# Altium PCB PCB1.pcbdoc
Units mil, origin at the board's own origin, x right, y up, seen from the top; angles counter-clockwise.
Board outline 4595.5 x 2040.6 mil, 2 copper layers (Top Layer, Bottom Layer), stack 62.2 mil thick; 83 components, 64 nets, 301 pads, 109 vias.
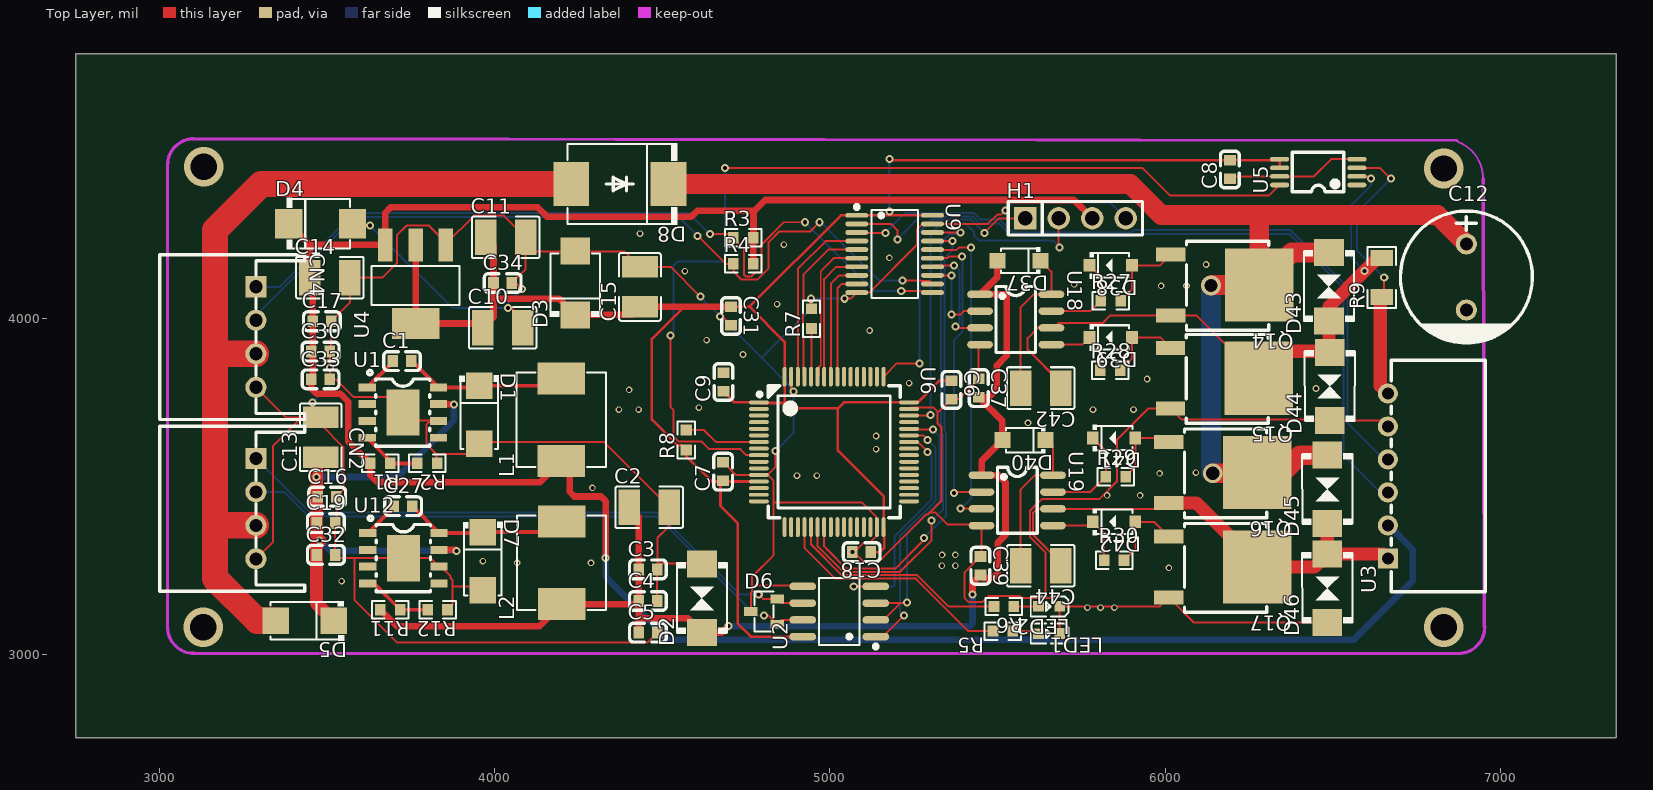
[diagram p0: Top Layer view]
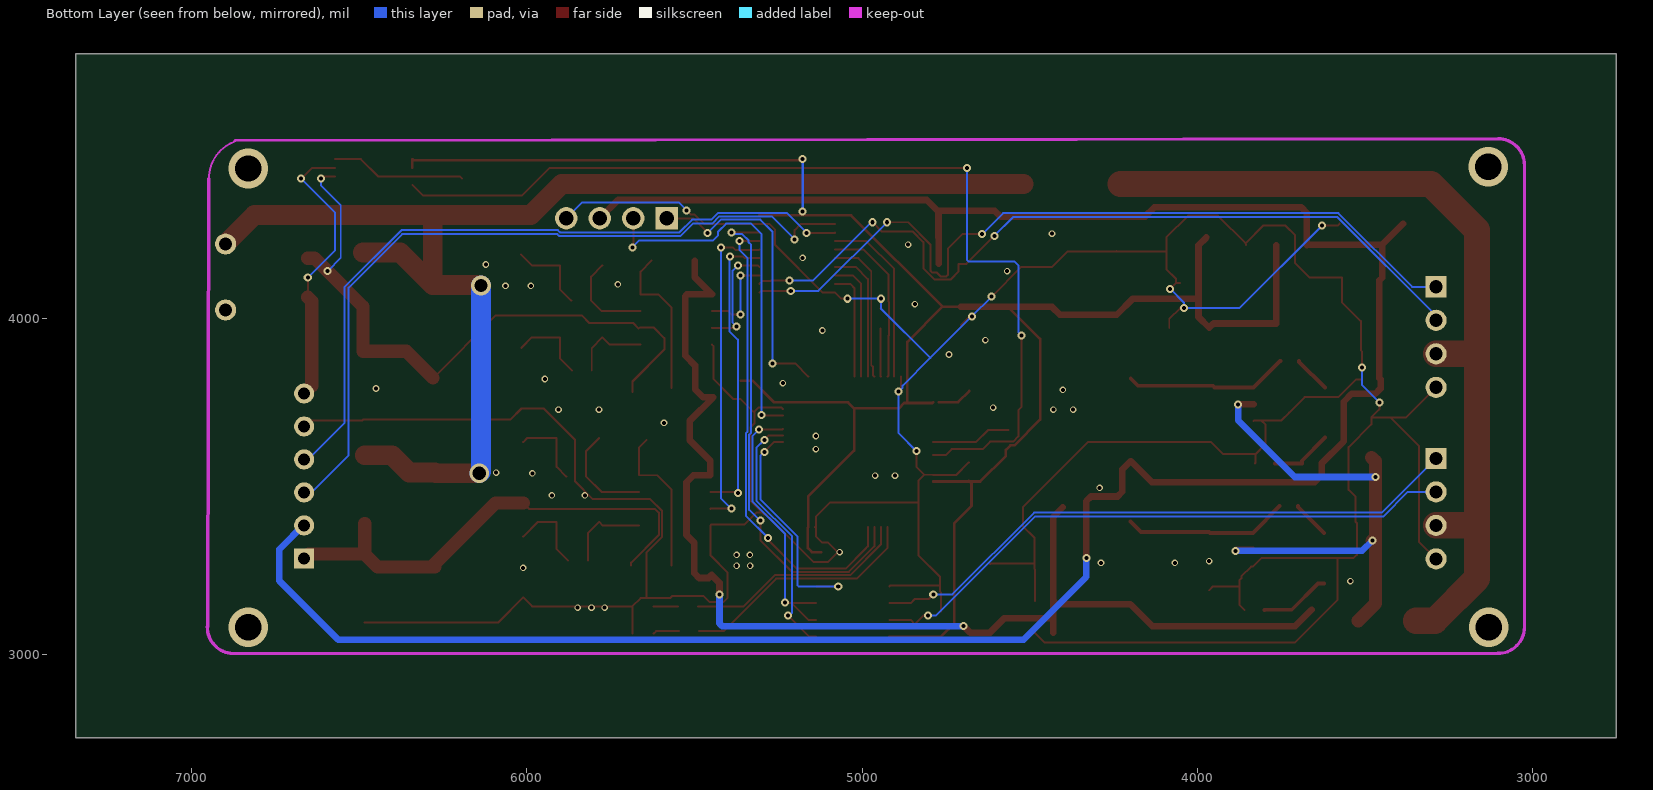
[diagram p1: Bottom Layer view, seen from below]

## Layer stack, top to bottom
Top Solder Mask Layer: solder mask 0.4, Dk 3.3
Top Layer: signal copper 1.4
Dielectric1: surface 59.4, FR4, Dk 4.5
Bottom Layer: signal copper 1.4
Bottom Solder Mask Layer: solder mask 0.4, Dk 3.3

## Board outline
7345.5,2750 2750,2750 2750,4790.6 7345.5,4790.6

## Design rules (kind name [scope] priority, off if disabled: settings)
BoardOutlineClearance copperThickness1oz [All] p0: genericclearance=10 ignorepadtopadclearanceinfootprint=FALSE except(0: Arc-SplitContinuation Track-SplitContinuation SMDPad-SplitContinuation THPad-SplitContinuation Via-SplitContinuation Fill-SplitContinuation Poly-SplitContinuation Region-SplitContinuation Text-SplitContinuation)
BoardOutlineClearance copperThickness2oz [All] p0: genericclearance=10 ignorepadtopadclearanceinfootprint=FALSE except(0: Arc-SplitContinuation Track-SplitContinuation SMDPad-SplitContinuation THPad-SplitContinuation Via-SplitContinuation Fill-SplitContinuation Poly-SplitContinuation Region-SplitContinuation Text-SplitContinuation)
BoardOutlineClearance otherClearance [All] p0: genericclearance=10 ignorepadtopadclearanceinfootprint=FALSE except(0: Arc-SplitContinuation Track-SplitContinuation SMDPad-SplitContinuation THPad-SplitContinuation Via-SplitContinuation Fill-SplitContinuation Poly-SplitContinuation Region-SplitContinuation Text-SplitContinuation)
Clearance copperThickness1oz [All] p1: gap=7 ignorepadtopadclearanceinfootprint=FALSE
Clearance copperThickness2oz [All] p1: gap=7 ignorepadtopadclearanceinfootprint=FALSE
Clearance otherClearance [All] p1: gap=7 ignorepadtopadclearanceinfootprint=FALSE
DiffPairsRouting differentialPair [All] p1: maxuncoupledlength=10 minlimit=6 maxlimit=Infinity mostfreqgap=6 toplayer_minwidth=5 toplayer_prefwidth=10 toplayer_maxwidth=100 bottomlayer_minwidth=5 bottomlayer_prefwidth=10 bottomlayer_maxwidth=100
PasteMaskExpansion pasteMaskExpansion [All] p1: expansion=0
PlaneConnect innerPlane [All] p1: planeconnectstyle=Direct reliefexpansion=20 reliefentries=4 reliefconductorwidth=10 reliefairgap=10
PolygonConnect copperRegion [All] p1: connectstyle=Direct reliefentries=4 reliefconductorwidth=10 polygonreliefangle="90 Angle" airgapwidth=10
RoutingVias viaSize [All] p1: viastyle="Through Hole" holewidth=12.0078 minholewidth=11.811 maxholewidth=248.0314 width=12.0078 minwidth=11.811 maxwidth=248.0314
SolderMaskExpansion solderMaskExpansion [IsVia] p1: useseparateexpansions=TRUE expansion=-1000 expansionbottom=-1000
SolderMaskExpansion solderMaskExpansion [All] p2: useseparateexpansions=TRUE expansion=2 expansionbottom=2
Width copperThickness1oz [All] p1: maxlimit=100 minlimit=5 preferedwidth=6
Width copperThickness2oz [All] p1: maxlimit=100 minlimit=8 preferedwidth=10
Width l24V [All] p1: maxlimit=100 minlimit=4 preferedwidth=39
Width i5V [All] p1: maxlimit=100 minlimit=5 preferedwidth=20
Width i3V [All] p1: maxlimit=100 minlimit=5 preferedwidth=8

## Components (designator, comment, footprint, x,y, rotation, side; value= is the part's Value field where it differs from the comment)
C1 "100nF" C0603#1 3723.3,3873.7 r0 top
C2 "10uF" C1210#1 4460.6,3437.7 r0 top
C3 "100nF" C0603#2 4456.7,3252.6 r0 top
C4 "100nF" C0603#2 4456.7,3158.1 r0 top
C5 "100nF" C0603#2 4456.7,3063.7 r0 top
C6 "100nF" C0603#1 5362.2,3788.1 r270 top
C7 "100nF" C0603#3 4681.1,3544 r90 top
C8 "100nF" C0603#3 6192.9,4445.6 r90 top
C9 "100nF" C0603#1 4682.3,3811.5 r90 top
C10 "10uF" C1210#1 4023.6,3973.1 r0 top
C11 "10uF" C1210#2 4032.2,4243 r0 top
C12 "470uF" CAP-TH_BD10.0-P5.00-D0.6-FD 6898.6,4124.7 r270 top
C13 "10uF" C1210#1 3480.3,3646.3 r90 top
C14 "10uF" C1210#3 3507.9,4122.7 r0 top
C15 "10uF" C1210#3 4433.1,4095.2 r90 top
C16 "100nF" C0603#2 3500,3469.2 r0 top
C17 "100nF" C0603#3 3484.3,3992.8 r0 top
C18 "100nF" C0603#1 5094.5,3303.8 r180 top
C19 "100nF" C0603#3 3496.1,3390.4 r0 top
C27 "100nF" C0603#3 3726.7,3440.9 r0 top
C30 "100nF" C0603#1 3480.3,3902.2 r0 top
C31 "100nF" C0603#3 4704.7,4008.5 r270 top
C32 "100nF" C0603#3 3496.1,3295.9 r0 top
C33 "100nF" C0603#1 3480.3,3819.6 r0 top
C34 "100nF" C0603#1 4023.6,4107 r0 top
C37 "100nF" C0603#2 5443.7,3793.3 r270 top
C39 "100nF" C0603#2 5448.7,3263.3 r270 top
C42 "10uF" C1210#3 5628.7,3793.3 r180 top
C44 "10uF" C1210#3 5628.7,3263.3 r180 top
CN2 "2.54-4P WZ-D" CONN-TH_2.54-4P-WZ-D 3287.4,3433.7 r270 top
CN4 "2.54-4P WZ-D" CONN-TH_2.54-4P-WZ-D 3287.4,3945.6 r270 top
D1 "B340A-E3/61T" SMA_L4.3-W2.6-LS5.2-RD 3953.3,3713.7 r270 top
D2 "SMBJ36CA" SMB_L4.6-W3.6-LS5.4-BI#1 4618.1,3166 r90 top
D3 "SMBJ5.0A" SMB_L4.6-W3.6-LS5.4-RD 4240.2,4107 r90 top
D4 "SMBJ5.0A" SMB_L4.6-W3.6-LS5.4-RD 3480.3,4284.1 r0 top
D5 "B340A-E3/61T" SMA_L4.3-W2.6-LS5.2-RD 3433.1,3099.1 r180 top
D6 "SM712" SOT-23-3_L2.9-W1.3-P1.90-LS2.4-BR 4803.1,3126.7 r0 top
D7 "B340A-E3/61T" SMA_L4.3-W2.6-LS5.2-RD 3964.4,3276.8 r270 top
D8 "B560C" SMC_L6.9-W5.9-LS7.9-RD 4373,4402.2 r180 top
D37 "FR107W" SOD-123FL_L2.7-W1.8-LS3.8-RD 5563.7,4173.3 r180 top
D38 "1N4148W" SOD-123_L2.7-W1.6-LS3.7-FD 5837.7,4159.4 r180 top
D39 "1N4148W" SOD-123_L2.7-W1.6-LS3.7-FD 5837.7,3944.4 r180 top
D40 "FR107W" SOD-123FL_L2.7-W1.8-LS3.8-RD 5578.7,3638.3 r180 top
D41 "1N4148W" SOD-123_L2.7-W1.6-LS3.7-FD 5847.7,3644.4 r180 top
D42 "1N4148W" SOD-123_L2.7-W1.6-LS3.7-FD 5847.7,3394.4 r180 top
D43 "SMBJ36CA" SMB_L4.6-W3.6-LS5.4-BI#2 6488.7,4096.1 r90 top
D44 "SMBJ36CA" SMB_L4.6-W3.6-LS5.4-BI#1 6490.7,3798.1 r90 top
D45 "SMBJ36CA" SMB_L4.6-W3.6-LS5.4-BI#2 6483.7,3491.1 r90 top
D46 "SMBJ36CA" SMB_L4.6-W3.6-LS5.4-BI#2 6483.7,3196.1 r90 top
H1 "PZ254V-11-04P" HDR-TH_4P-P2.54-V-M 5732.3,4299.9 r0 top
L1 "22uH" IND-SMD_L7.0-W6.6_FXL0630 4198.3,3698.7 r90 top
L2 "22uH" IND-SMD_L7.0-W6.6_FXL0630 4199.4,3271.8 r90 top
LED1 "" LED_0603 5651.6,3060.7 r180 top
LED2 "" LED_0603 5651.6,3141.8 r180 top
Q14 "CMD100N08A" TO-252-3_L6.5-W5.8-P4.58-LS9.5-BR#1 6148.7,4101.1 r180 top
Q15 "CMD100N08A" TO-252-3_L6.5-W5.8-P4.58-LS9.5-BR#1 6147.7,3823 r180 top
Q16 "CMD100N08A" TO-252-3_L6.5-W5.8-P4.58-LS9.5-BR#2 6142.7,3541.3 r180 top
Q17 "CMD100N08A" TO-252-3_L6.5-W5.8-P4.58-LS9.5-BR#1 6142.7,3259.5 r180 top
R1 "10K" R0603#1 3658.3,3568.7 r180 top
R2 "10K" R0603#1 3798.3,3568.7 r180 top
R3 "10K" R0603#1 4741.2,4241.8 r0 top
R4 "10K" R0603#1 4741.2,4164.1 r0 top
R5 "10K" R0603#2 5516,3068.5 r180 top
R6 "10K" R0603#1 5518.7,3141.8 r180 top
R7 "10kΩ" R0603#1 4944.9,4000.7 r90 top
R8 "10kΩ" R0603#1 4570.9,3638.5 r90 top
R9 "10mΩ" R1206 6645.7,4122.7 r90 top
R11 "10K" R0603#2 3688.4,3132.1 r180 top
R12 "10K" R0603#3 3829.4,3131.8 r180 top
R27 "10K" R0603#1 5837.7,4054.4 r0 top
R28 "10K" R0603#2 5835.9,3846.3 r0 top
R29 "10K" R0603#1 5852.7,3529.4 r0 top
R30 "10K" R0603#1 5847.7,3279.4 r0 top
U1 "TPS5430DDAR" ESOP-8_L4.9-W3.9-P1.27-LS6.0-TL-EP 3725.6,3720.3 r0 top
U2 "SP3485EEN(UMW)" SOP-8_L5.0-W4.0-P1.27-LS6.0-BL 5027.6,3126.7 r90 top
U3 "WAFER-XH254WZ-6A" CONN-TH_6P-P2.50_WAFER-XH254WZ-6A 6664.4,3531.2 r90 top
U4 "AMS1117-3.3" SOT-223-3_L6.5-W3.4-P2.30-LS7.0-BR 3763.8,4103 r90 top
U5 "INA240A1PWR" TSSOP-8_L4.4-W3.0-P0.65-LS6.4-BL 6456.7,4437.7 r90 top
U6 "STM32F103RCT6" LQFP-64_L10.0-W10.0-P0.50-LS12.0-BL 5011.8,3603 r270 top
U9 "74HC245PW,118" TSSOP-20_L6.5-W4.4-P0.65-LS6.4-BL 5192.9,4193.6 r270 top
U12 "TPS5430DDAR" ESOP-8_L4.9-W3.9-P1.27-LS6.0-TL-EP 3727.5,3285.8 r0 top
U18 "EG2104S" SOIC-8_L5.0-W4.0-P1.27-LS6.0-BL 5554.1,3997.9 r270 top
U19 "EG2104S" SOIC-8_L5.0-W4.0-P1.27-LS6.0-BL 5558.7,3458.3 r270 top

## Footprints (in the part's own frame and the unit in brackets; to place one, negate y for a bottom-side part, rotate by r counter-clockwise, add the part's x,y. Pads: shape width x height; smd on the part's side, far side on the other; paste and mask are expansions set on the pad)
C0603#1 [mil]
  rect 31.5x35.4 smd: 1(-27.5,0) 2(27.6,0)
  silkscreen extent -55,-28 55,28
C0603#2 [mil]
  rect 31.5x35.4 smd: 1(-27.6,0) 2(27.6,0)
  silkscreen extent -55,-28 55,28
C0603#3 [mil]
  rect 31.5x35.4 smd: 1(-27.6,0) 2(27.5,0)
  silkscreen extent -55,-28 55,28
C1210#1 [mil]
  rect 64.4x106.3 smd paste-3937 mask+2: 1(-59.7,0) 2(59.8,0)
  silkscreen extent -101,-62 101,62
C1210#2 [mil]
  rect 64.4x106.3 smd paste-3937 mask+2: 1(-59.7,0) 2(59.7,0)
  silkscreen extent -101,-62 101,62
C1210#3 [mil]
  rect 64.4x106.3 smd paste-3937 mask+2: 1(-59.8,0) 2(59.7,0)
  silkscreen extent -101,-62 101,62
CAP-TH_BD10.0-P5.00-D0.6-FD [mil]
  round 63 hole 39.4 paste+0 mask+2: 1(-98.4,0) 2(98.4,0)
  silkscreen extent -197,-197 200,197
CONN-TH_2.54-4P-WZ-D [mil]
  rect 63x63 hole 39.4 paste+0 mask+2: 1(-150,0)
  round 63 hole 39.4 paste+0 mask+2: 2(-50,0) 3(50,0) 4(150,0)
  silkscreen extent -246,-287 246,146
CONN-TH_6P-P2.50_WAFER-XH254WZ-6A [mil]
  rect 60x60 hole 36: 1(-246.1,0)
  round 60 hole 36: 2(-147.7,0) 3(-49.2,0) 4(49.2,0) 5(147.6,0) 6(246,0)
  silkscreen extent -345,-290 345,-10
ESOP-8_L4.9-W3.9-P1.27-LS6.0-TL-EP [mm]
  rect 1.3x0.599 smd: 1(-2.7,1.905) 2(-2.7,0.635) 3(-2.7,-0.635) 4(-2.7,-1.905) 5(2.7,-1.905) 6(2.7,-0.635) 7(2.7,0.635) 8(2.7,1.905)
  rect 2.499x3.5 smd: 9(0,0)
  silkscreen extent -2.67,-2.55 2.05,3.2
HDR-TH_4P-P2.54-V-M [mil]
  rect 66.9x66.9 hole 43.3: 1(-150,0)
  round 66.9 hole 43.3: 2(-50,0) 3(50,0) 4(150,0)
  silkscreen extent -200,-50 200,50
IND-SMD_L7.0-W6.6_FXL0630 [mil]
  rect 95.4x142.5 smd: 1(123.1,0) 2(-123.2,0)
  silkscreen extent -141,-133 141,133
LED_0603 [mil]
  rect 31.5x31.5 smd paste+0 mask+2: 1(-33.5,-0.4) 2(29.5,-0.2)
  silkscreen extent -61,-30 53,30
LQFP-64_L10.0-W10.0-P0.50-LS12.0-BL [mil]
  oval 11.8x59.1 smd: 1(-147.7,-223.9) 2(-128,-223.9) 3(-108.3,-223.9) 4(-88.6,-223.9) 5(-68.9,-223.9) 6(-49.2,-223.9) 7(-29.6,-223.9) 8(-9.9,-223.9) 9(9.8,-223.9) 10(29.5,-223.9) 11(49.2,-223.9) 12(68.9,-223.9) 13(88.5,-223.9) 14(108.2,-223.9) 15(127.9,-223.9) 16(147.6,-223.9) 33(147.6,224) 34(127.9,224) 35(108.2,224) 36(88.5,224) 37(68.9,224) 38(49.2,224) 39(29.5,224) 40(9.8,224) 41(-9.9,224) 42(-29.6,224) 43(-49.2,224) 44(-68.9,224) 45(-88.6,224) 46(-108.3,224) 47(-128,224) 48(-147.7,224)
  oval 59.1x11.8 smd: 17(224.4,-147.2) 18(224.4,-127.5) 19(224.4,-107.8) 20(224.4,-88.1) 21(224.4,-68.4) 22(224.4,-48.7) 23(224.4,-29.1) 24(224.4,-9.4) 25(224.4,10.3) 26(224.4,30) 27(224.4,49.7) 28(224.4,69.4) 29(224.4,89.1) 30(224.4,108.7) 31(224.4,128.4) 32(224.4,148.1) 49(-224.4,148.1) 50(-224.4,128.4) 51(-224.4,108.7) 52(-224.4,89.1) 53(-224.4,69.4) 54(-224.4,49.7) 55(-224.4,30) 56(-224.4,10.3) 57(-224.4,-9.4) 58(-224.4,-29.1) 59(-224.4,-48.7) 60(-224.4,-68.4) 61(-224.4,-88.1) 62(-224.4,-107.8) 63(-224.4,-127.5) 64(-224.4,-147.2)
  silkscreen extent -197,-228 197,197
R0603#1 [mil]
  rect 31.8x34 smd paste-3937 mask+2: 1(-29.7,0) 2(29.6,0)
  silkscreen extent -55,-26 54,26
R0603#2 [mil]
  rect 31.8x34 smd paste-3937 mask+2: 1(-29.6,0) 2(29.7,0)
  silkscreen extent -54,-26 55,26
R0603#3 [mil]
  rect 31.8x34 smd paste-3937 mask+2: 1(-29.7,0) 2(29.7,0)
  silkscreen extent -54,-26 54,26
R1206 [mil]
  rect 47.5x67 smd paste-3937 mask+2: 1(-58.2,0) 2(58.2,0)
  silkscreen extent -91,-43 91,43
SMA_L4.3-W2.6-LS5.2-RD [mil]
  rect 78.7x78.7 smd: 1(-86.6,0) 2(86.6,0)
  silkscreen extent -117,-59 102,59
SMB_L4.6-W3.6-LS5.4-BI#1 [mil]
  rect 80.6x88.2 smd: 1(-102,0) 2(102,0)
  silkscreen extent -105,-75 108,75
SMB_L4.6-W3.6-LS5.4-BI#2 [mil]
  rect 80.6x88.2 smd: 1(-102.1,0) 2(102,0)
  silkscreen extent -105,-75 108,75
SMB_L4.6-W3.6-LS5.4-RD [mil]
  rect 80.6x88.2 smd: 1(-95,0) 2(95,0)
  silkscreen extent -100,-77 88,77
SMC_L6.9-W5.9-LS7.9-RD [mil]
  rect 106.3x129.9 smd: 1(-145.2,0) 2(145.1,0)
  silkscreen extent -172,-122 157,122
SOD-123_L2.7-W1.6-LS3.7-FD [mil]
  rect 34.6x37.8 smd: 1(-63.4,0) 2(63.4,0)
  silkscreen extent -54,-39 63,40
SOD-123FL_L2.7-W1.8-LS3.8-RD [mil]
  rect 47.2x47.2 smd: 1(-64.4,0) 2(64.3,0)
  silkscreen extent -63,-40 54,39
SOIC-8_L5.0-W4.0-P1.27-LS6.0-BL [mil]
  oval 22.4x76.8 smd: 1(-75,-106.5) 2(-25,-106.5) 3(25,-106.5) 4(75,-106.5) 5(75,106.5) 6(25,106.5) 7(-25,106.5) 8(-75,106.5)
  silkscreen extent -98,-59 98,59
SOP-8_L5.0-W4.0-P1.27-LS6.0-BL [mil]
  oval 22.6x80.1 smd: 1(-75,-108.9) 2(-25,-108.9) 3(25,-108.9) 4(75,-108.9) 5(75,109) 6(25,109) 7(-25,109) 8(-75,109)
  silkscreen extent -110,-115 99,60
SOT-23-3_L2.9-W1.3-P1.90-LS2.4-BR [mil]
  rect 39.4x25.6 smd: 1(39.4,-37.4) 2(39.4,37.4) 3(-39.3,0)
  silkscreen extent -28,-60 29,60
SOT-223-3_L6.5-W3.4-P2.30-LS7.0-BR [mil]
  rect 98.4x43.3 smd: 1(117,-90.5) 2(117,0) 3(117,90.6)
  rect 92.1x141.7 smd: 4(-116.9,0)
  silkscreen extent -62,-131 54,131
TO-252-3_L6.5-W5.8-P4.58-LS9.5-BR#1 [mil]
  rect 87.3x41.9 smd: 1(131.8,-90.5) 3(131.8,90.6)
  rect 204.9x218.6 smd: 2(-131.9,0)
  silkscreen extent -160,-130 85,135
TO-252-3_L6.5-W5.8-P4.58-LS9.5-BR#2 [mil]
  rect 87.3x41.9 smd: 1(131.8,-90.6) 3(131.8,90.5)
  rect 204.9x218.6 smd: 2(-131.9,0)
  silkscreen extent -160,-130 85,135
TSSOP-8_L4.4-W3.0-P0.65-LS6.4-BL [mil]
  oval 13.9x57.2 smd: 1(-38.4,-115.2) 2(-12.8,-115.2) 3(12.8,-115.2) 4(38.4,-115.2) 5(38.4,115.2) 6(12.8,115.2) 7(-12.8,115.2) 8(-38.4,115.2)
  silkscreen extent -59,-76 59,77
TSSOP-20_L6.5-W4.4-P0.65-LS6.4-BL [mil]
  oval 14.3x68.6 smd: 1(-115.1,-113) 2(-89.6,-113) 3(-64,-113) 4(-38.4,-113) 5(-12.8,-113) 6(12.8,-113) 7(38.4,-113) 8(64,-113) 9(89.6,-113) 10(115.2,-113) 11(115.2,113) 12(89.6,113) 13(64,113) 14(38.4,113) 15(12.8,113) 16(-12.8,113) 17(-38.4,113) 18(-64,113) 19(-89.6,113) 20(-115.1,113)
  silkscreen extent -146,-119 131,70

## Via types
v1: diameter 24, hole 12, Top Layer to Bottom Layer, 59 vias
v2: diameter 19.7, hole 12, Top Layer to Bottom Layer, 44 vias
v3: diameter 118.1, hole 78.7, Top Layer to Bottom Layer, 4 vias
v4: diameter 59.1, hole 39.4, Top Layer to Bottom Layer, 2 vias

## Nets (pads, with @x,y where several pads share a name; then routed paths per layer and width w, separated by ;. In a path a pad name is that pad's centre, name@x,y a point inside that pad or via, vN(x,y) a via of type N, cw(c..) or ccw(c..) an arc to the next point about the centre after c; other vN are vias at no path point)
3.3V: C6.1 C7.1 C8.2 C9.1 C10.1 C11.1 C15.1 C18.1 C31.1 C34.1 D3.1 R8.1 U2.8 U4.2 U4.4 U5.5 U5.6 U6.1 U6.13 U6.32 U6.48 U6.64 U9.1 U9.20 | length 6564.1
  Top Layer w7.9: 4564,4035.4 4468.5,3939.9 4468.5,3699.1 4544.9,3622.7 4557,3622.7 R8.1 4570.9,3591.2 4647.6,3514.5 C7.1@4679.1,3514.5 ; C9.1@4679.8,3785.2 4713.7,3751.3 U6.1@4771.5,3751.3 ; C7.1 C7.1@4679.1,3514.5 ; C31.1 4759.8,4036.1 ; U6.13 C7.1@4679.1,3514.5 ; U6.1 4789.8,3748.7 4865.1,3748.7 ; U2.8 4764,3051.7 4724.4,3091.2 4724.4,3390.4 4673.2,3441.6 4673.2,3508.5 C7.1@4679.1,3514.5 ; C18.1 5149.6,3303.8 5161.4,3315.6 5161.4,3377.1 U6.32 5159.9,3470.7 5023.6,3607 5023.6,3733 ; v1(5177.2,4319.6) 5188,4308.7 ; v1(5177.2,4477) 5181.1,4473.1 C8.2 6338.5,4473.1 U5.5 U5.6 ; U9.20 5188,4308.7 ; C6.1 5326.8,3815.6 5261.8,3750.7 U6.48 5041.3,3750.7 5023.6,3733 ; 4759.8,4036.1 5032.5,4308.7 U9.1 5188,4308.7 ; 4759.8,4036.1 4864.6,3931.3 U6.64 4864.6,3749.2 4865.1,3748.7 ; 4865.1,3748.7 4874,3748.7 4889.8,3733 5023.6,3733
  Top Layer w19.7: U4.2 U4.4 3950.9,3986.1 C10.1 3996.1,4005.3 3996.1,4060.4 ; C11.1 3996.1,4219.4 C34.1 3996.1,4060.4 ; C31.1 4704,4035.4 4564,4035.4 C15.1 4409.6,4012 D3.1 4191.7,4060.4 3996.1,4060.4
  Bottom Layer w7.9: v1(5177.2,4319.6) v1(5177.2,4477)
12V: C2.1 C3.1 C4.1 C5.1 C37.2 C39.2 D2.1 D37.2 D40.2 L2.2 R11.2 U18.1 U19.1 | length 3658.1
  Top Layer w19.7: R11.2 3707.5,3083.3 4134.1,3083.3 L2.2 4419.6,3148.6 C4.1 ; C2.1 4429.1,3409.4 C3.1 C4.1 ; C5.1 4429.1,3115.6 ; v1(4696.8,3083.3) 4677.5,3064 D2.1 4575.1,3107 4437.8,3107 4429.1,3115.6 ; v1(5425.2,3177.8) 5425.2,3212.2 C39.2 5457.6,3226.9 5486.1,3226.9 5500,3240.8 5500,3331.4 5523.6,3355 5523.6,3512.5 5502.8,3533.3 U19.1 5452.2,3576.2 D40.2 5514.4,3695.1 C37.2 5473.7,3765.7 5498,3790 5498,3860.9 5527.6,3890.4 5527.6,4067.6 5522.2,4072.9 U18.1 5499.4,4124.7 D37.2 ; 4429.1,3115.6 C4.1
  Bottom Layer w19.7: v1(4696.8,3083.3) 5417.3,3083.3 5425.2,3091.2 v1(5425.2,3177.8)
24V: C13.1 C16.1 C19.1 C32.1 D5.1 U1.7 U12.7 | length 1565.6
  Top Layer w19.7: U1.7 3877.5,3745.3 v1(3878,3744.8) ; U12.7 3882.8,3310.8 v1(3885.8,3307.8)
  Top Layer w39.4: v1(3476.4,3339.3) v1@3478.5,3337.1 ; C13.1 3468.5,3574.8 v1(3468.5,3528.2) C19.1 C32.1 3468.5,3150.3 D5.1
  Bottom Layer w19.7: v1(3468.5,3528.2) 3708.7,3528.2 3878,3697.5 v1(3878,3744.8) ; v1(3476.4,3339.3) 3507.9,3307.8 v1(3885.8,3307.8)
24V-M: C12.1 D8.1 D43.2 D45.2 Q14.2 Q16.2 | length 3983.1
  Top Layer w59.1: D8.1 5895.7,4402.2 5988.2,4309.7 6282.2,4309.7 ; v4(6136.8,4099.1) 6138.8,4101.1 Q14.2 ; v4(6141.7,3539.1) 6272.3,3539.1 Q16.2 6350.7,3541.3 6402.5,3593.1 D45.2 ; D43.2 6377.6,4198.1 Q14.2 ; C12.1 6812,4309.7 6282.2,4309.7 ; Q14.2 6280.6,4308.1 6282.2,4309.7
  Bottom Layer w59.1: v4(6136.8,4099.1) 6136.8,3544 v4(6141.7,3539.1)
24V-P: CN2.3 CN4.3 D5.2 D8.2 | length 2637.3
  Top Layer w78.7: CN2.3 3287.2,3383.6 3165.1,3383.6 ; CN4.3 3165.1,3895.6 ; D5.2 3291.1,3099.1 3165.1,3225.1 3165.1,3383.6 ; D8.2 3303.1,4402.2 3165.1,4264.2 3165.1,3895.6 ; 3165.1,3383.6 3165.1,3895.6
$1N1: C1.1 U1.1 | length 110.1
  Top Layer w11.8: U1.1 3695.8,3871.7 C1.1
$1N2: C27.1 U12.1 | length 112.4
  Top Layer w11.8: U12.1 3699.1,3438.7 C27.1
$1N3: C1.2 D1.1 L1.1 U1.8 | length 490.9
  Top Layer w11.8: C1.2 3753.5,3873.7 U1.8 3948.3,3795.3 D1.1 4176.8,3800.3 L1.1
$1N4: C27.2 D7.1 L2.1 U12.8 | length 492.8
  Top Layer w11.8: C27.2 3833.8,3361.3 U12.8 3961.8,3360.8 D7.1 4167.9,3363.4 L2.1
$1N7: R1.1 R2.2 U1.4 | length 185.8
  Top Layer w11.8: U1.4 3688,3576.6 R1.1 R2.2
$1N8: R11.1 R12.2 U12.4 | length 211.3
  Top Layer w11.8: U12.4 3639.4,3210.8 R11.1 3799.4,3132.1 R12.2
$1N71: U6.57 U9.8 | length 365.1
  Top Layer w5.9: U6.57 5002.4,4104.6 5027.4,4129.6 U9.8
$1N72: U6.58 U9.7 | length 403.6
  Top Layer w5.9: U6.58 4982.7,4118.7 5019.3,4155.2 U9.7
$1N73: U6.59 U9.6 | length 442.1
  Top Layer w5.9: U6.59 4967.9,3832.3 4967.9,3857.2 4972.4,3861.7 4972.4,4142.1 5011.1,4180.8 U9.6
$1N74: U6.61 U9.5 | length 497.5
  Top Layer w5.9: U6.61 4921.3,3829.9 4921.3,3949.1 4918.9,3951.4 4918.9,4049.9 4921.3,4052.2 4921.3,4132.8 4994.8,4206.4 U9.5
$1N75: U6.62 U9.4 | length 532.1
  Top Layer w5.9: U6.62 4904,4149.3 4986.7,4232 U9.4
$1N90: C44.2 D40.1 U19.8 | length 455.5
  Top Layer w5.9: C44.2 5569,3490.9 5611.4,3533.3 U19.8 5665.2,3616.2 D40.1
$1N92: H1.1 U6.49 | length 881.3
  Top Layer w5.9: U6.49 5199.3,3866.8 v1(5267.7,3866.8) ; v1(5460.6,4256.6) 5503.9,4299.9 H1.1
  Bottom Layer w5.9: v1(5267.7,3866.8) 5267.7,4260.5 5303.1,4295.9 5421.3,4295.9 v1(5460.6,4256.6)
$1N93: H1.2 U6.46 | length 1126.3
  Top Layer w5.9: U6.46 5297.2,3711.3 v1(5299.2,3713.3) ; H1.2 5682.3,4216 v1(5685,4213.3)
  Bottom Layer w5.9: v1(5299.2,3713.3) 5299.2,4252.6 5330.7,4284.1 5405.5,4284.1 5429.1,4260.5 5429.1,4248.7 5444.9,4233 5665.4,4233 v1(5685,4213.3)
$1N120: D38.1 Q14.1 R27.2 | length 248.2
  Top Layer w5.9: R27.2 5901.1,4088.1 D38.1 5984.7,4159.4 Q14.1
$1N121: D41.1 Q16.1 R29.2 | length 231.9
  Top Layer w5.9: R29.2 5911.1,3558.1 D41.1 5998.4,3644.4 Q16.1
$1N122: D42.1 Q17.1 R30.2 | length 247.3
  Top Layer w5.9: R30.2 5911.1,3313.1 D42.1 5966.6,3394.4 Q17.1
$1N123: D39.1 Q15.1 R28.2 | length 240.4
  Top Layer w5.9: R28.2 5901.1,3881.8 D39.1 5985.1,3944.4 Q15.1
$1N124: D38.2 R27.1 U18.7 | length 279.4
  Top Layer w5.9: U18.7 5776.6,4022.9 R27.1 5808,4125.6 D38.2
$1N125: D39.2 R28.1 U18.5 | length 234
  Top Layer w5.9: U18.5 5752.8,3922.9 D39.2 5806.3,3912.4 R28.1
$1N126: D41.2 R29.1 U19.7 | length 307.9
  Top Layer w5.9: U19.7 5777,3483.3 R29.1 5823,3605.6 D41.2
$1N127: D42.2 R30.1 U19.5 | length 252.6
  Top Layer w5.9: U19.5 5773.2,3383.3 D42.2 5818,3360.6 R30.1
$1N128: C42.2 D37.1 U18.8 | length 462.4
  Top Layer w5.9: C42.2 5569,4034.2 5607.7,4072.9 U18.8 5660.6,4140.8 D37.1
$1N138: R8.2 U6.7 | length 239.5
  Top Layer w5.9: R8.2@4563,3667.9 4624.1,3667.9 4659.4,3632.6 U6.7
$1N139: R7.1 U6.60 | length 144.2
  Top Layer w5.9: U6.60 4944.9,3828.9 R7.1
$1N154: U6.30
$1N155: U6.29
$1N156: U6.28
$1N157: U6.27
$1N158: U6.26
$1N159: R6.2 U6.21 | length 674.2
  Top Layer w5.9: U6.21 4943.4,3326.7 5035.1,3235 5260,3235 5353.2,3141.8 R6.2
$1N160: R5.2 U6.20 | length 727.1
  Top Layer w5.9: U6.20 4923.7,3317.1 5015.7,3225.1 5255.9,3225.1 5412.5,3068.5 R5.2
$1N221: U6.56 U9.9 | length 326.5
  Top Layer w5.9: U6.56 5022.1,4090.5 5035.6,4104 U9.9
$1N223: LED1.2 R5.1 | length 79.6
  Top Layer w5.9: R5.1 5614.4,3068.5 LED1.2
$1N227: LED2.2 R6.1 | length 73.8
  Top Layer w5.9: R6.1 5621.9,3141.8 LED2.2
$1N253: U6.17
+5V: C14.1 C17.1 C30.1 C33.1 D4.1 H1.3 L1.2 R1.2 R3.2 R4.2 U3.2 U4.3 | length 7359.1
  Top Layer w19.7: D4.1 3448.1,4221.3 ; v1(4330.8,3287.1) 4330.8,3456.1 4316.9,3470 4237.3,3470 4223.4,3483.9 4223.4,3550.4 L1.2 4135.3,3512.5 3649.6,3512.5 3628.7,3533.4 R1.2 3563,3634.4 3563,3752.6 3539.4,3776.3 3468.5,3776.3 3452.8,3792 C33.1 3456.7,3823.5 C17.1 3456.7,4114.2 C14.1 3448.1,4221.3 ; R4.2 R3.2 4771.7,4242.6 4771.7,4319.6 ; H1.3 5727.6,4354.6 4806.6,4354.6 4771.7,4319.6 ; 3448.1,4221.3 3671.9,4221.3 U4.3 3673.2,4316.6 3689,4332.4 4128,4332.4 4155.5,4304.8 4586.6,4304.8 4604.3,4322.5 4768.7,4322.5 4771.7,4319.6
  Bottom Layer w19.7: v1(4330.8,3287.1) 4330.8,3229.9 4517.7,3043 6563,3043 6738.2,3218.2 6738.2,3312.7 U3.2@6661.4,3389.4
A: U6.22 U9.18 | length 1527.5
  Top Layer w5.9: U6.22 4963.1,3321.1 5039.2,3244.9 5208.8,3244.9 5303.1,3339.3 5303.1,3396.6 v1@5304,3397.5 ; U9.18 v1(5389.8,4257.6)
  Bottom Layer w5.9: v1@5304,3397.5 5336.7,3430.2 5336.7,3654.4 5330.7,3660.4 5330.7,4221.1 5338.6,4229 5338.6,4234 5357.5,4252.9 5385.1,4252.9 v1(5389.8,4257.6)
  other v1: 5303.1,3398.4
A485: CN2.1 D6.2 U2.6 | length 1810.1
  Top Layer w5.9: v1(4787.4,3177.8) 4801.2,3164.1 D6.2 4854.9,3151.7 U2.6
  Bottom Layer w5.9: CN2.1 3449.2,3421.9 4486.5,3421.9 4730.6,3177.8 v1(4787.4,3177.8)
ADC1_IN1_IA: U5.8 U6.9 | length 2932.3
  Top Layer w5.9: v1(4523.7,3950.4) 4523.7,3737.6 4533.8,3727.5 4533.8,3649.2 4549.4,3633.6 4617.6,3633.6 4640.2,3611.1 4732.6,3611.1 4750.4,3593.2 U6.9 ; v1(4686.4,4450.4) 5931.3,4450.4 6013.6,4368 6310.2,4368 U5.8
  Bottom Layer w5.9: v1(4523.7,3950.4) 4533.8,3960.4 4533.8,4159.2 4545.8,4171.3 4682.4,4171.3 4686.4,4175.3 v1(4686.4,4450.4)
AO: U3.3 U9.2 | length 2255.2
  Top Layer w5.9: U9.2 5182.1,4283.2 5200.8,4264.4 v1(5200.8,4236.9)
  Bottom Layer w5.9: v1(5200.8,4236.9) 5269.8,4305.9 5425.4,4305.9 5447.1,4284.1 5504.4,4284.1 5541,4247.6 5904,4247.6 5909,4252.6 6372,4252.6 6531.5,4093.1 6531.5,3593.2 U3.3@6635.8,3488.9
B: U6.23 U9.17 | length 1410.5
  Top Layer w5.9: U6.23 4982.4,3378.3 4982.4,3321.4 4992.5,3311.3 4992.5,3310.8 5048.5,3254.8 5195.1,3254.8 5280.5,3340.2 v1(5280.5,3346.2) ; U9.17 v1(5366.1,4232)
  Bottom Layer w5.9: v1(5280.5,3346.2) 5346.6,3412.3 5346.6,3658.5 5341.3,3663.8 5341.3,4180.5 5366.1,4205.4 v1(5366.1,4232)
B485: CN2.2 D6.1 U2.7 | length 1799.7
  Top Layer w5.9: v1(4803.1,3114.8) 4816.9,3114.8 D6.1 4854.9,3101.7 U2.7
  Bottom Layer w5.9: CN2.2 3371.3,3483.7 3444.9,3410.1 4484.3,3410.1 4779.5,3114.8 v1(4803.1,3114.8)
BO: U3.4 U9.3 | length 2169.2
  Top Layer w5.9: U9.3 5080.9,4256.6 v1(5165.4,4256.6)
  Bottom Layer w5.9: v1(5165.4,4256.6) 5224.6,4315.8 5429.5,4315.8 5449.3,4295.9 5506.7,4295.9 5545.1,4257.5 5899.8,4257.5 5907.1,4264.7 6373.9,4264.7 6543.3,4095.3 6543.3,3689.6 6661.4,3571.5 U3.4@6661.4,3560.7
DE: U2.2 U2.3 U6.44 | length 824.7
  Top Layer w5.9: U2.2 5160,3101.7 5210,3151.7 ; U2.3 5210,3151.7 ; v1(5229.6,3154.2) 5227,3151.7 5210,3151.7 ; U6.44 5237.7,3670 v1(5307.1,3670)
  Bottom Layer w5.9: v1(5229.6,3154.2) 5229.6,3358 5326.8,3455.1 5326.8,3650.3 v1(5307.1,3670)
GND: C2.2 C3.2 C4.2 C5.2 C6.2 C7.2 C8.1 C9.2 C10.2 C11.2 C12.2 C13.2 C14.2 C15.2 C16.2 C17.2 C18.2 C19.2 C30.2 C31.2 C32.2 C33.2 C34.2 C37.1 C39.1 CN2.4 CN4.4 D1.2 D2.2 D3.2 D4.2 D6.3 D7.2 D44.1 D46.1 H1.4 LED1.1 LED2.1 Q15.3 Q17.3 R2.1 R7.2 R12.1 U1.6 U1.9 U2.5 U3.5 U4.1 U5.4 U5.7 U6.12 U6.31 U6.47 U6.63 U9.10 U9.19 U12.6 U12.9 U18.4 U19.4 | length 15234.1
  Top Layer w5.9: CN2.4 3337.6,3333.9 3337.6,3619.5 3424.2,3706.1 ; CN4.4@3287.4,3795.5 3376.9,3706.1 3424.2,3706.1 ; v1(3456.7,3750.7) 3456.7,3729.7 C13.2 ; D4.2 3581.2,4278.2 v1(3627.7,4278.2) ; R2.1 3826,3570.7 3826,3596.2 ; U1.6 3830.5,3696.6 U1.6@3808.3,3696.6 ; U4.1 U4.1@3855.7,4225.3 ; R12.1 3874.2,3146.9 3874.2,3201.7 ; D7.2 3952.8,3201.7 3874.2,3201.7 ; v1(4039.4,4031.9) 4051.2,4031.9 4083.4,3999.7 C10.2 ; C34.2 C34.2@4063,4107 ; v1(4080.7,4089.3) C34.2@4063,4107 ; D3.2 D3.2@4240.2,4201.5 ; C5.2 4454.7,3034.1 3708.7,3034.1 3581,3161.8 3581,3285.8 ; C4.2 C3.2 4484.9,3253.3 C3.2@4484.9,3269.4 ; v1(4613.2,4066.3) 4524.6,4154.9 C15.2 4386.5,4201.5 D3.2@4240.2,4201.5 ; D2.2 4616.8,3269.4 C3.2@4484.9,3269.4 ; v1(4672.2,4007.3) 4678.4,4007.3 C31.2 ; C7.2 4718.5,3534.1 U6.12 4788.6,3534.8 U6.12@4814,3534.8 ; D6.3 4763.8,3183.4 4766.7,3186.4 4766.7,3204.1 ; v1(4837.6,3605.7) 4837.6,3558.4 U6.12@4814,3534.8 ; U6.63 4884.3,3789.3 v1(4890.7,3782.9) ; U2.5 4916.1,3204.1 4766.7,3204.1 ; v1(4943.3,4059.9) 4943.3,4031.9 R7.2 ; v1(5043.7,4059.9) 5061.3,4059.9 U9.10 5117.1,4078.4 5258.9,4220.2 5258.9,4265.6 5276.6,4283.3 U9.19@5305.8,4283.3 ; v2(5066.9,3303.8) C18.2@5072.8,3303.8 ; U6.31 U6.31@5137.8,3376.2 ; U6.47 5239.7,3734.9 5309.1,3734.9 5320.9,3723.1 ; U9.19 5471.3,4283.2 5499.8,4311.7 5511.6,4311.7 v1(5523.5,4323.5) ; U18.4 5443.7,3919 C37.1 5383.4,3760.5 C6.2 5324.8,3723.1 5320.9,3723.1 ; LED1.1 LED2.1 ; C8.1 6199.8,4424.9 U5.7 6443.9,4424.9 6495.1,4476.1 U5.4 ; D46.1 6085.8,3094 Q17.3 5984.2,3142.2 LED2.1 ; D44.1@6488.7,3699 6049.3,3699 Q15.3 5949.3,3732.4 5856.2,3639.3 5856.2,3515.3 5803.1,3462.1 5631.8,3462.1 5596.4,3426.7 5596.4,3349.9 5643.6,3302.7 5643.6,3166.9 ; D44.1 6647.1,3696.1 U3.5 ; 3424.2,3706.1 C13.2 ; C13.2 3480.3,3685.4 3548.2,3617.5 3548.2,3489.8 C16.2 3527.6,3394.4 C19.2 C32.2 3533.8,3285.8 3581,3285.8 ; 3581,3285.8 U12.9 3808.8,3285.8 U12.6 3838.8,3260.8 3868.3,3231.3 3868.3,3225.4 3874.2,3219.5 3874.2,3201.7 ; U1.6@3808.3,3696.6 3796.5,3684.8 3796.5,3625.8 3826,3596.2 ; U1.6@3808.3,3696.6 3749.2,3696.6 U1.9 3679.4,3766.4 3578.7,3766.4 3525.6,3819.6 C33.2 v1(3507.9,3855) C30.2 3511.8,3906.2 C17.2 3567.6,4048.6 C14.2 3664.5,4122.7 3708.1,4166.2 3708.1,4248.9 3737.6,4278.4 3802.6,4278.4 U4.1@3855.7,4225.3 ; 3826,3596.2 3922.5,3596.2 3953.3,3627 3959.2,3633 4325.1,3633 C2.2 4520.4,3381.6 4484.9,3346.1 C3.2@4484.9,3269.4 ; U4.1@3855.7,4225.3 3938.4,4308 4027,4308 C11.2 C11.2@4091.9,4200.9 ; C34.2@4063,4107 4063,4118.8 4091.9,4147.7 C11.2@4091.9,4200.9 ; C11.2@4091.9,4200.9 4239.6,4200.9 D3.2@4240.2,4201.5 ; 4766.7,3204.1 4766.7,3229.7 4831.7,3294.7 4831.7,3452.1 ; U6.12@4814,3534.8 4831.7,3517.1 4831.7,3452.1 ; 4831.7,3452.1 5094.8,3452.1 5137.8,3409.1 U6.31@5137.8,3376.2 ; C18.2@5072.8,3303.8 5102.4,3333.3 5120.1,3333.3 5137.8,3351.1 U6.31@5137.8,3376.2 ; C18.2@5072.8,3303.8 5102.4,3274.3 5143.7,3274.3 5285.4,3416 5291.3,3416 5297.2,3421.9 ; 5297.2,3421.9 5315,3421.9 5350.4,3386.5 5449,3386.5 U19.4 5452.2,3294.4 C39.1 5401.5,3243.6 5401.5,3166.9 5413.3,3155 5454.6,3155 5472.4,3172.8 5566.8,3172.8 5572.8,3166.9 5643.6,3166.9 ; 5297.2,3421.9 5332.7,3457.4 5332.7,3675.9 5320.9,3687.7 5320.9,3723.1 ; 5643.6,3166.9 5660.4,3166.9 LED2.1
  Bottom Layer w5.9: v1(3456.7,3750.7) 3507.9,3801.8 v1(3507.9,3855) ; v1(3627.7,4278.2) 3874,4031.9 v1(4039.4,4031.9) 4039.4,4047.9 v1(4080.7,4089.3) ; v1(4613.2,4066.3) v1(4672.2,4007.3) 4796.3,3883.2 ; v1(4837.6,3605.7) 4890.7,3658.8 v1(4890.7,3782.9) 4878.9,3794.7 4878.9,3800.6 4796.3,3883.2 ; v1(5043.7,4059.9) v1(4943.3,4059.9) 4943.3,4030.3 4796.3,3883.2 ; v1(5523.5,4323.5) 5547.1,4347.1 5835,4347.1 H1.4
  other v2: 5767.7,3138.5 5807.1,3138.5 5848.5,3138.5 3543.3,3217.2 6010.9,3257 5333.7,3263.3 5374,3263.3 4066.5,3271.8 4287.1,3271.8 3964.4,3276.8 5334.6,3295.9 5374,3295.9 5826.8,3473.1 5925.2,3473.1 4291.3,3495.7 4901.6,3532.2 4960.6,3532.2 5983.2,3538.8 6091.5,3541.3 5137.8,3610.9 5137.8,3650.3 5590.6,3689.6 4370.1,3729 4429.1,3729 5784.6,3729 5905.5,3729 4608.5,3734.9 4400.9,3788.1 6449.8,3792 5236.2,3807.8 5946.2,3820.5 4740.5,3893.5 4631.9,3936.1 5118.1,3965.2 4842.5,4044 5988.2,4098.6 6063.7,4098.6 5728.3,4103 4566.9,4142.4 6122,4162.1 5177.2,4181.8 4862.2,4221.1 4433.1,4253.9
IN1: CN4.2 R4.1 U9.12 | length 2437.6
  Top Layer w5.9: v1(4605.3,4247.7) 4688.9,4164.1 R4.1 4711.5,4141.3 4736,4116.7 4783,4116.7 4817,4150.7 4817,4228.8 4848.7,4260.5 4940.9,4260.5 v1(4968.5,4288.1) ; v1(5216.5,4114.8) 5270.8,4114.8 5272.1,4113.5 5296.5,4113.5 U9.12
  Bottom Layer w5.9: CN4.2 3287.4,4008.5 3582.7,4303.8 4549.2,4303.8 v1(4605.3,4247.7) ; v1(4968.5,4288.1) 4972.4,4288.1 5145.7,4114.8 v1(5216.5,4114.8)
IN2: CN4.1 R3.1 U9.11 | length 2433.3
  Top Layer w5.9: v1(4641.7,4252.6) 4700.7,4252.6 R3.1 4744.1,4209.2 4744.1,4130.8 4748.3,4126.7 4765.8,4126.7 4777.3,4138.1 4790.4,4138.1 4795.6,4143.4 4795.6,4221.5 4862.2,4288.1 v1(4925.2,4288.1) ; v1(5212.6,4083.3) 5301,4083.3 U9.11
  Bottom Layer w5.9: CN4.1 3358.7,4095.6 3578.7,4315.6 4578.7,4315.6 v1(4641.7,4252.6) ; v1(4925.2,4288.1) 5129.9,4083.3 v1(5212.6,4083.3)
key1: U6.15
key2: U6.16
M1A: R9.1 U3.6 U5.3 | length 845.8
  Top Layer w5.9: U5.3 6640.7,4450.5 v1(6673.2,4418) ; R9.1@6653.5,4064.5 v1(6653.5,4122.7)
  Top Layer w39.4: R9.1@6653.5,4064.5 6641.7,4052.7 6641.7,3799.9 U3.6
  Bottom Layer w5.9: v1(6653.5,4122.7) 6571.7,4204.5 6571.7,4316.5 v1(6673.2,4418)
M1B: C44.1 D45.1 D46.2 Q16.3 Q17.2 U3.1 U19.6 | length 1460.1
  Top Layer w5.9: C44.1 5688.5,3272.8 5606.3,3355 5606.3,3421.9 5617.7,3433.3 U19.6 5993.5,3433.3 Q16.3
  Top Layer w39.4: Q16.3 6093.2,3450.8 6274.6,3269.4 Q17.2 6445.1,3259.5 D46.2 ; D45.1 D46.2 ; U3.1 6651.4,3298.1 D46.2
PWMD1O: U9.13 U18.2 | length 263.1
  Top Layer w5.9: U9.13 v1(5362.2,4129.6) ; v1(5362.2,4012.5) 5388.6,4012.5 5399,4022.9 U18.2
  Bottom Layer w5.9: v1(5362.2,4012.5) v1(5362.2,4129.6)
PWMD2O: U9.15 U19.2 | length 889
  Top Layer w5.9: U9.15 5349.4,4180.8 5354.3,4185.7 v1(5393.7,4185.7) ; v1(5370.1,3481) 5372.4,3483.3 U19.2
  Bottom Layer w5.9: v1(5370.1,3481) 5370.1,3937.7 5395.7,3963.3 5395.7,4183.7 v1(5393.7,4185.7)
RX: U2.1 U6.43 | length 756
  Top Layer w5.9: U2.1 5157.3,3051.7 v1(5220.5,3114.8) ; U6.43 5277.6,3652.2 v1(5291.3,3638.5)
  Bottom Layer w5.9: v1(5220.5,3114.8) 5216.5,3114.8 5208.7,3122.7 5208.7,3351.1 5315,3457.4 5315,3614.8 v1(5291.3,3638.5)
SDD1O: U9.14 U18.3 | length 335.6
  Top Layer w5.9: U9.14 5310.4,4159.6 v1(5370.1,4159.6) ; v1@5373.8,3977.3 5378,3973.1 5447.4,3973.1 U18.3
  Bottom Layer w5.9: v1(5370.1,4159.6) 5385.8,4143.9 5385.8,3988.9 v1(5374,3977)
SDD2O: U9.16 U19.3 | length 974.3
  Top Layer w5.9: U9.16 5306.9,4205.4 5378,4205.4 5385.8,4213.3 v1(5421.3,4213.3) ; v1(5389.8,3433.7) 5451.8,3433.7 U19.3
  Bottom Layer w5.9: v1(5389.8,3433.7) 5421.3,3465.2 v1(5421.3,4213.3)
SHA: C42.1 D43.1 D44.2 Q14.3 Q15.2 R9.2 U5.2 U18.6 | length 1952.8
  Top Layer w5.9: U18.6@5662.7,3973.5 5620.6,3973.5 5589.4,3942.3 5589.4,3908.4 5684.7,3813 C42.1@5684.7,3781.8 ; U18.6@5667.2,3971.7 5683.1,3987.5 5813.9,3987.5 5836.5,4010.2 Q14.3@6015.6,4010.2 ; Q14.3 6092,4010.5 Q15.2 ; U5.2 6607.3,4424.9 v1(6614.2,4418)
  Top Layer w39.4: Q15.2 6359.7,3903.1 6488.7,3903.1 D43.1 6488.7,4036.7 v1(6594.5,4142.4) 6633,4180.9 R9.2@6653.5,4180.9
  Bottom Layer w5.9: v1(6594.5,4142.4) 6555.1,4181.8 6555.1,4339.3 6614.2,4398.3 v1(6614.2,4418)
TX: U2.4 U6.42 | length 705.2
  Top Layer w5.9: v1(5070.9,3201.5) 5136.3,3201.5 U2.4 ; U6.42 5261.8,3632.6 v1(5291.3,3603)
  Bottom Layer w5.9: v1(5070.9,3201.5) 5189,3201.5 5192.9,3205.4 5192.9,3351.1 5303.1,3461.3 5303.1,3591.2 v1(5291.3,3603)
pads on no net: U1.2 U1.3 U1.5 U5.1 U6.2 U6.3 U6.4 U6.5 U6.6 U6.8 U6.10 U6.11 U6.14 U6.18 U6.19 U6.24 U6.25 U6.33 U6.34 U6.35 U6.36 U6.37 U6.38 U6.39 U6.40 U6.41 U6.45 U6.50 U6.51 U6.52 U6.53 U6.54 U6.55 U12.2 U12.3 U12.5
copper on no net:
  other v3: 3129.9,3079.4 6830.7,3079.4 6830.7,4448.4 3131.5,4453.1

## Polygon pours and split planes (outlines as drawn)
GND on Top Layer (solid, remove dead copper, pour order 0): 3019.9,4540.6 3019.9,3002 6956.9,3002 6956.9,4540.6
GND on Bottom Layer (solid, remove dead copper, pour order 2): 3010.7,4538.6 3010.7,3000 6947.7,3000 6947.7,4538.6

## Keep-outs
Board Outline Layer:
  lines w5.9: 6854.7,4533.6 6863.9,4531.3 6872.9,4528.3 6881.6,4524.6 6890,4520.1 6898.1,4515 6905.6,4509.3 6912.7,4503 6919.3,4496.1 6925.3,4488.8 6930.7,4480.9 6935.4,4472.7 6939.4,4464.1 6942.8,4455.2 6945.4,4446.1 6947.3,4436.8 6948.4,4427.4 6948.8,4417.9
  lines w10: 3023.6,3080.2 3024,3072.4 3025.2,3064.7 3027.2,3057.1 3029.9,3049.7 3033.3,3042.7 3037.4,3036 3042.1,3029.8 3047.4,3024.1 3053.3,3018.9 3059.6,3014.3 3066.4,3010.4 3073.5,3007.2 3080.9,3004.7 3088.5,3003 3096.3,3002 3104.1,3001.8 ; 3023.6,3080.5 3023.6,4458.4 ; 3023.6,4458.8 3024,4466.5 3025.2,4474.1 3027.1,4481.6 3029.7,4488.8 3033,4495.8 3037,4502.4 3041.6,4508.5 3046.8,4514.2 3052.5,4519.4 3058.7,4524 3065.3,4527.9 3072.3,4531.2 3079.6,4533.8 3087,4535.7 3094.7,4536.8 3102.4,4537.2 6870.3,4532.1 ; 3102.4,3001.7 6875.8,3001.7 ; 6876.9,3001.4 6884.5,3002 6892,3003.4 6899.3,3005.5 6906.5,3008.3 6913.3,3011.7 6919.7,3015.8 6925.7,3020.5 6931.2,3025.8 6936.2,3031.6 6940.6,3037.8 6944.5,3044.4 6947.6,3051.4 6950.1,3058.6 6951.8,3066 6952.8,3073.6 6953.1,3081.2 ; 6948.8,4418 6952.4,3081.6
